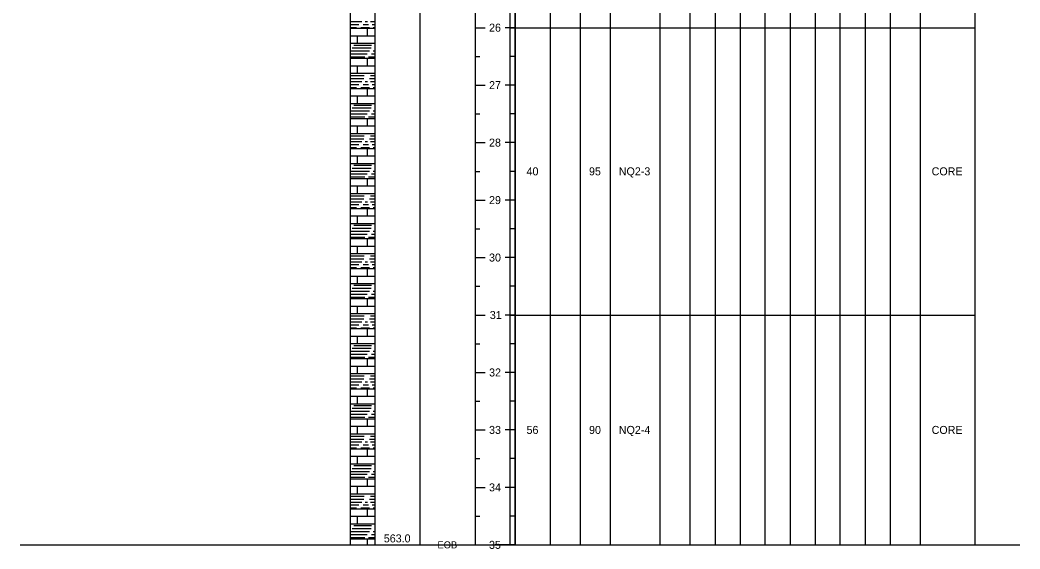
# Model space of a CAD drawing. Extents: x -0.01 to 0.83, y -0.48 to 1.27.
# Drawn here: x 0 to 0.833, y -0.482 to -0.041 of the extents above; entities that cross this region are included whole.
import ezdxf

# ---------------------------------------------------------------- set-up
doc = ezdxf.new("R2010")
doc.units = 0

msp = doc.modelspace()

# ---------------------------------------------------------------- linework, layer by layer
for points in [[(0.29583, 1.22083), (0.29583, -0.47833)], [(0.29583, 1.22083), (0.29583, -0.47833)], [(0.33333, 1.22083), (0.33333, -0.47833)], [(0.33333, 1.22083), (0.33333, -0.47833)], [(0.4125, 1.22083), (0.4125, -0.47833)], [(0.4125, 1.22083), (0.4125, -0.47833)], [(0.44167, 1.22083), (0.44167, -0.47833)], [(0.46667, 1.22083), (0.46667, -0.47833)], [(0.49167, 1.22083), (0.49167, -0.47833)], [(0.53333, 1.22083), (0.53333, -0.47833)], [(0.55833, 1.22083), (0.55833, -0.47833)], [(0.6625, 1.22083), (0.6625, -0.47833)], [(0.725, 1.22083), (0.725, -0.47833)], [(0.75, 1.22083), (0.75, -0.47833)], [(0.75, 1.22083), (0.75, -0.47833)], [(0.79583, 1.22083), (0.79583, -0.47833)], [(0.57917, 1.20833), (0.57917, -0.47833)], [(0.6, 1.20833), (0.6, -0.47833)], [(0.62083, 1.20833), (0.62083, -0.47833)], [(0.64167, 1.20833), (0.64167, -0.47833)], [(0.68333, 1.20833), (0.68333, -0.47833)], [(0.70417, 1.20833), (0.70417, -0.47833)], [(0.725, 1.20833), (0.725, -0.47833)], [(0.275, 1.19583), (0.275, -0.47833)], [(0.37917, 1.19583), (0.37917, -0.47833)], [(0.275, 0.23917), (0.275, -0.47833)], [(0.40833, 0.19133), (0.40833, -0.04783)], [(0.275, -0.04267), (0.28483, -0.04267)], [(0.275, -0.04508), (0.28233, -0.04508)], [(0.275, -0.04758), (0.28033, -0.04758)], [(0.275, -0.04833), (0.29583, -0.04833)], [(0.284, -0.04758), (0.29133, -0.04758)], [(0.286, -0.04508), (0.2905, -0.04508)], [(0.28767, -0.04267), (0.28967, -0.04267)], [(0.28958, -0.05458), (0.28958, -0.04833)], [(0.29217, -0.04267), (0.29583, -0.04267)], [(0.29342, -0.04508), (0.29583, -0.04508)], [(0.29417, -0.04758), (0.29583, -0.04758)], [(0.37917, -0.04783), (0.3875, -0.04783)], [(0.37917, -0.04783), (0.38333, -0.04783)], [(0.4125, -0.04783), (0.40417, -0.04783)], [(0.40833, -0.04783), (0.4125, -0.04783)], [(0.40833, -0.04783), (0.40833, -0.287)], [(0.40833, -0.04783), (0.4125, -0.04783)], [(0.4125, -0.04783), (0.40833, -0.04783)], [(0.4125, -0.04783), (0.44167, -0.04783)], [(0.44167, -0.04783), (0.46667, -0.04783)], [(0.46667, -0.04783), (0.49167, -0.04783)], [(0.49167, -0.04783), (0.53333, -0.04783)], [(0.53333, -0.04783), (0.55833, -0.04783)], [(0.55833, -0.04783), (0.57917, -0.04783)], [(0.57917, -0.04783), (0.6, -0.04783)], [(0.6, -0.04783), (0.62083, -0.04783)], [(0.62083, -0.04783), (0.64167, -0.04783)], [(0.64167, -0.04783), (0.6625, -0.04783)], [(0.6625, -0.04783), (0.68333, -0.04783)], [(0.68333, -0.04783), (0.70417, -0.04783)], [(0.70417, -0.04783), (0.725, -0.04783)], [(0.725, -0.04783), (0.75, -0.04783)], [(0.75, -0.04783), (0.79583, -0.04783)], [(0.275, -0.05458), (0.29583, -0.05458)], [(0.28125, -0.06083), (0.28125, -0.05458)], [(0.275, -0.06083), (0.29583, -0.06083)], [(0.27667, -0.06467), (0.29258, -0.06467)], [(0.27825, -0.06225), (0.293, -0.06225)], [(0.29542, -0.06225), (0.29583, -0.06225)], [(0.275, -0.06717), (0.29133, -0.06717)], [(0.275, -0.06958), (0.28933, -0.06958)], [(0.275, -0.07208), (0.28725, -0.07208)], [(0.275, -0.07333), (0.29583, -0.07333)], [(0.28958, -0.07958), (0.28958, -0.07333)], [(0.2905, -0.07208), (0.29583, -0.07208)], [(0.293, -0.06958), (0.29583, -0.06958)], [(0.29417, -0.06717), (0.29583, -0.06717)], [(0.37917, -0.07175), (0.38333, -0.07175)], [(0.4125, -0.07175), (0.40833, -0.07175)], [(0.275, -0.07958), (0.29583, -0.07958)], [(0.28125, -0.08583), (0.28125, -0.07958)], [(0.275, -0.08583), (0.29583, -0.08583)], [(0.275, -0.08775), (0.28683, -0.08775)], [(0.275, -0.09025), (0.28642, -0.09025)], [(0.29133, -0.09025), (0.29583, -0.09025)], [(0.29217, -0.08775), (0.29583, -0.08775)], [(0.275, -0.09267), (0.28483, -0.09267)], [(0.275, -0.09508), (0.28233, -0.09508)], [(0.275, -0.09758), (0.28033, -0.09758)], [(0.275, -0.09833), (0.29583, -0.09833)], [(0.284, -0.09758), (0.29133, -0.09758)], [(0.286, -0.09508), (0.2905, -0.09508)], [(0.28767, -0.09267), (0.28967, -0.09267)], [(0.28958, -0.10458), (0.28958, -0.09833)], [(0.29217, -0.09267), (0.29583, -0.09267)], [(0.29342, -0.09508), (0.29583, -0.09508)], [(0.29417, -0.09758), (0.29583, -0.09758)], [(0.37917, -0.09567), (0.3875, -0.09567)], [(0.37917, -0.09567), (0.38333, -0.09567)], [(0.4125, -0.09567), (0.40417, -0.09567)], [(0.4125, -0.09567), (0.40833, -0.09567)], [(0.275, -0.10458), (0.29583, -0.10458)], [(0.28125, -0.11083), (0.28125, -0.10458)], [(0.275, -0.11083), (0.29583, -0.11083)], [(0.27667, -0.11467), (0.29258, -0.11467)], [(0.27825, -0.11225), (0.293, -0.11225)], [(0.29542, -0.11225), (0.29583, -0.11225)], [(0.275, -0.11717), (0.29133, -0.11717)], [(0.275, -0.11958), (0.28933, -0.11958)], [(0.275, -0.12208), (0.28725, -0.12208)], [(0.275, -0.12333), (0.29583, -0.12333)], [(0.28958, -0.12958), (0.28958, -0.12333)], [(0.2905, -0.12208), (0.29583, -0.12208)], [(0.293, -0.11958), (0.29583, -0.11958)], [(0.29417, -0.11717), (0.29583, -0.11717)], [(0.37917, -0.11958), (0.38333, -0.11958)], [(0.4125, -0.11958), (0.40833, -0.11958)], [(0.275, -0.12958), (0.29583, -0.12958)], [(0.28125, -0.13583), (0.28125, -0.12958)], [(0.275, -0.13583), (0.29583, -0.13583)], [(0.275, -0.13775), (0.28683, -0.13775)], [(0.275, -0.14025), (0.28642, -0.14025)], [(0.29133, -0.14025), (0.29583, -0.14025)], [(0.29217, -0.13775), (0.29583, -0.13775)], [(0.275, -0.14267), (0.28483, -0.14267)], [(0.275, -0.14508), (0.28233, -0.14508)], [(0.275, -0.14758), (0.28033, -0.14758)], [(0.275, -0.14833), (0.29583, -0.14833)], [(0.284, -0.14758), (0.29133, -0.14758)], [(0.286, -0.14508), (0.2905, -0.14508)], [(0.28767, -0.14267), (0.28967, -0.14267)], [(0.28958, -0.15458), (0.28958, -0.14833)], [(0.29217, -0.14267), (0.29583, -0.14267)], [(0.29342, -0.14508), (0.29583, -0.14508)], [(0.29417, -0.14758), (0.29583, -0.14758)], [(0.37917, -0.1435), (0.3875, -0.1435)], [(0.37917, -0.1435), (0.38333, -0.1435)], [(0.4125, -0.1435), (0.40417, -0.1435)], [(0.4125, -0.1435), (0.40833, -0.1435)], [(0.275, -0.15458), (0.29583, -0.15458)], [(0.28125, -0.16083), (0.28125, -0.15458)], [(0.275, -0.16083), (0.29583, -0.16083)], [(0.27667, -0.16467), (0.29258, -0.16467)], [(0.27825, -0.16225), (0.293, -0.16225)], [(0.29542, -0.16225), (0.29583, -0.16225)], [(0.275, -0.16717), (0.29133, -0.16717)], [(0.275, -0.16958), (0.28933, -0.16958)], [(0.275, -0.17208), (0.28725, -0.17208)], [(0.275, -0.17333), (0.29583, -0.17333)], [(0.28958, -0.17958), (0.28958, -0.17333)], [(0.2905, -0.17208), (0.29583, -0.17208)], [(0.293, -0.16958), (0.29583, -0.16958)], [(0.29417, -0.16717), (0.29583, -0.16717)], [(0.37917, -0.16742), (0.38333, -0.16742)], [(0.4125, -0.16742), (0.40833, -0.16742)], [(0.275, -0.17958), (0.29583, -0.17958)], [(0.28125, -0.18583), (0.28125, -0.17958)], [(0.275, -0.18583), (0.29583, -0.18583)], [(0.275, -0.18775), (0.28683, -0.18775)], [(0.275, -0.19025), (0.28642, -0.19025)], [(0.29133, -0.19025), (0.29583, -0.19025)], [(0.29217, -0.18775), (0.29583, -0.18775)], [(0.37917, -0.19133), (0.3875, -0.19133)], [(0.37917, -0.19133), (0.38333, -0.19133)], [(0.4125, -0.19133), (0.40417, -0.19133)], [(0.4125, -0.19133), (0.40833, -0.19133)], [(0.275, -0.19267), (0.28483, -0.19267)], [(0.275, -0.19508), (0.28233, -0.19508)], [(0.275, -0.19758), (0.28033, -0.19758)], [(0.275, -0.19833), (0.29583, -0.19833)], [(0.284, -0.19758), (0.29133, -0.19758)], [(0.286, -0.19508), (0.2905, -0.19508)], [(0.28767, -0.19267), (0.28967, -0.19267)], [(0.28958, -0.20458), (0.28958, -0.19833)], [(0.29217, -0.19267), (0.29583, -0.19267)], [(0.29342, -0.19508), (0.29583, -0.19508)], [(0.29417, -0.19758), (0.29583, -0.19758)], [(0.275, -0.20458), (0.29583, -0.20458)], [(0.28125, -0.21083), (0.28125, -0.20458)], [(0.275, -0.21083), (0.29583, -0.21083)], [(0.27667, -0.21467), (0.29258, -0.21467)], [(0.27825, -0.21225), (0.293, -0.21225)], [(0.29542, -0.21225), (0.29583, -0.21225)], [(0.37917, -0.21525), (0.38333, -0.21525)], [(0.4125, -0.21525), (0.40833, -0.21525)], [(0.275, -0.21717), (0.29133, -0.21717)], [(0.275, -0.21958), (0.28933, -0.21958)], [(0.275, -0.22208), (0.28725, -0.22208)], [(0.275, -0.22333), (0.29583, -0.22333)], [(0.28958, -0.22958), (0.28958, -0.22333)], [(0.2905, -0.22208), (0.29583, -0.22208)], [(0.293, -0.21958), (0.29583, -0.21958)], [(0.29417, -0.21717), (0.29583, -0.21717)], [(0.275, -0.22958), (0.29583, -0.22958)], [(0.28125, -0.23583), (0.28125, -0.22958)], [(0.275, -0.23583), (0.29583, -0.23583)], [(0.275, -0.23775), (0.28683, -0.23775)], [(0.275, -0.24025), (0.28642, -0.24025)], [(0.29133, -0.24025), (0.29583, -0.24025)], [(0.29217, -0.23775), (0.29583, -0.23775)], [(0.37917, -0.23917), (0.3875, -0.23917)], [(0.37917, -0.23917), (0.38333, -0.23917)], [(0.4125, -0.23917), (0.40417, -0.23917)], [(0.4125, -0.23917), (0.40833, -0.23917)], [(0.275, -0.24267), (0.28483, -0.24267)], [(0.275, -0.24508), (0.28233, -0.24508)], [(0.275, -0.24758), (0.28033, -0.24758)], [(0.275, -0.24833), (0.29583, -0.24833)], [(0.284, -0.24758), (0.29133, -0.24758)], [(0.286, -0.24508), (0.2905, -0.24508)], [(0.28767, -0.24267), (0.28967, -0.24267)], [(0.28958, -0.25458), (0.28958, -0.24833)], [(0.29217, -0.24267), (0.29583, -0.24267)], [(0.29342, -0.24508), (0.29583, -0.24508)], [(0.29417, -0.24758), (0.29583, -0.24758)], [(0.275, -0.25458), (0.29583, -0.25458)], [(0.28125, -0.26083), (0.28125, -0.25458)], [(0.275, -0.26083), (0.29583, -0.26083)], [(0.27667, -0.26467), (0.29258, -0.26467)], [(0.27825, -0.26225), (0.293, -0.26225)], [(0.29542, -0.26225), (0.29583, -0.26225)], [(0.37917, -0.26308), (0.38333, -0.26308)], [(0.4125, -0.26308), (0.40833, -0.26308)], [(0.275, -0.26717), (0.29133, -0.26717)], [(0.275, -0.26958), (0.28933, -0.26958)], [(0.275, -0.27208), (0.28725, -0.27208)], [(0.275, -0.27333), (0.29583, -0.27333)], [(0.28958, -0.27958), (0.28958, -0.27333)], [(0.2905, -0.27208), (0.29583, -0.27208)], [(0.293, -0.26958), (0.29583, -0.26958)], [(0.29417, -0.26717), (0.29583, -0.26717)], [(0.275, -0.27958), (0.29583, -0.27958)], [(0.28125, -0.28583), (0.28125, -0.27958)], [(0.275, -0.28583), (0.29583, -0.28583)], [(0.275, -0.28775), (0.28683, -0.28775)], [(0.275, -0.29025), (0.28642, -0.29025)], [(0.29133, -0.29025), (0.29583, -0.29025)], [(0.29217, -0.28775), (0.29583, -0.28775)], [(0.37917, -0.287), (0.3875, -0.287)], [(0.37917, -0.287), (0.38333, -0.287)], [(0.4125, -0.287), (0.40417, -0.287)], [(0.40833, -0.287), (0.4125, -0.287)], [(0.40833, -0.287), (0.40833, -0.47833)], [(0.40833, -0.287), (0.4125, -0.287)], [(0.4125, -0.287), (0.40833, -0.287)], [(0.4125, -0.287), (0.44167, -0.287)], [(0.44167, -0.287), (0.46667, -0.287)], [(0.46667, -0.287), (0.49167, -0.287)], [(0.49167, -0.287), (0.53333, -0.287)], [(0.53333, -0.287), (0.55833, -0.287)], [(0.55833, -0.287), (0.57917, -0.287)], [(0.57917, -0.287), (0.6, -0.287)], [(0.6, -0.287), (0.62083, -0.287)], [(0.62083, -0.287), (0.64167, -0.287)], [(0.64167, -0.287), (0.6625, -0.287)], [(0.6625, -0.287), (0.68333, -0.287)], [(0.68333, -0.287), (0.70417, -0.287)], [(0.70417, -0.287), (0.725, -0.287)], [(0.725, -0.287), (0.75, -0.287)], [(0.75, -0.287), (0.79583, -0.287)], [(0.275, -0.29267), (0.28483, -0.29267)], [(0.275, -0.29508), (0.28233, -0.29508)], [(0.275, -0.29758), (0.28033, -0.29758)], [(0.275, -0.29833), (0.29583, -0.29833)], [(0.284, -0.29758), (0.29133, -0.29758)], [(0.286, -0.29508), (0.2905, -0.29508)], [(0.28767, -0.29267), (0.28967, -0.29267)], [(0.28958, -0.30458), (0.28958, -0.29833)], [(0.29217, -0.29267), (0.29583, -0.29267)], [(0.29342, -0.29508), (0.29583, -0.29508)], [(0.29417, -0.29758), (0.29583, -0.29758)], [(0.275, -0.30458), (0.29583, -0.30458)], [(0.28125, -0.31083), (0.28125, -0.30458)], [(0.275, -0.31083), (0.29583, -0.31083)], [(0.27667, -0.31467), (0.29258, -0.31467)], [(0.27825, -0.31225), (0.293, -0.31225)], [(0.29542, -0.31225), (0.29583, -0.31225)], [(0.37917, -0.31092), (0.38333, -0.31092)], [(0.4125, -0.31092), (0.40833, -0.31092)], [(0.275, -0.31717), (0.29133, -0.31717)], [(0.275, -0.31958), (0.28933, -0.31958)], [(0.275, -0.32208), (0.28725, -0.32208)], [(0.275, -0.32333), (0.29583, -0.32333)], [(0.28958, -0.32958), (0.28958, -0.32333)], [(0.2905, -0.32208), (0.29583, -0.32208)], [(0.293, -0.31958), (0.29583, -0.31958)], [(0.29417, -0.31717), (0.29583, -0.31717)], [(0.275, -0.32958), (0.29583, -0.32958)], [(0.28125, -0.33583), (0.28125, -0.32958)], [(0.275, -0.33583), (0.29583, -0.33583)], [(0.275, -0.33775), (0.28683, -0.33775)], [(0.275, -0.34025), (0.28642, -0.34025)], [(0.29133, -0.34025), (0.29583, -0.34025)], [(0.29217, -0.33775), (0.29583, -0.33775)], [(0.37917, -0.33483), (0.3875, -0.33483)], [(0.37917, -0.33483), (0.38333, -0.33483)], [(0.4125, -0.33483), (0.40417, -0.33483)], [(0.4125, -0.33483), (0.40833, -0.33483)], [(0.275, -0.34267), (0.28483, -0.34267)], [(0.275, -0.34508), (0.28233, -0.34508)], [(0.275, -0.34758), (0.28033, -0.34758)], [(0.275, -0.34833), (0.29583, -0.34833)], [(0.284, -0.34758), (0.29133, -0.34758)], [(0.286, -0.34508), (0.2905, -0.34508)], [(0.28767, -0.34267), (0.28967, -0.34267)], [(0.28958, -0.35458), (0.28958, -0.34833)], [(0.29217, -0.34267), (0.29583, -0.34267)], [(0.29342, -0.34508), (0.29583, -0.34508)], [(0.29417, -0.34758), (0.29583, -0.34758)], [(0.275, -0.35458), (0.29583, -0.35458)], [(0.28125, -0.36083), (0.28125, -0.35458)], [(0.275, -0.36083), (0.29583, -0.36083)], [(0.27667, -0.36467), (0.29258, -0.36467)], [(0.27825, -0.36225), (0.293, -0.36225)], [(0.29542, -0.36225), (0.29583, -0.36225)], [(0.37917, -0.35875), (0.38333, -0.35875)], [(0.4125, -0.35875), (0.40833, -0.35875)], [(0.275, -0.36717), (0.29133, -0.36717)], [(0.275, -0.36958), (0.28933, -0.36958)], [(0.275, -0.37208), (0.28725, -0.37208)], [(0.275, -0.37333), (0.29583, -0.37333)], [(0.28958, -0.37958), (0.28958, -0.37333)], [(0.2905, -0.37208), (0.29583, -0.37208)], [(0.293, -0.36958), (0.29583, -0.36958)], [(0.29417, -0.36717), (0.29583, -0.36717)], [(0.275, -0.37958), (0.29583, -0.37958)], [(0.28125, -0.38583), (0.28125, -0.37958)], [(0.37917, -0.38267), (0.3875, -0.38267)], [(0.37917, -0.38267), (0.38333, -0.38267)], [(0.4125, -0.38267), (0.40417, -0.38267)], [(0.4125, -0.38267), (0.40833, -0.38267)], [(0.275, -0.38583), (0.29583, -0.38583)], [(0.275, -0.38775), (0.28683, -0.38775)], [(0.275, -0.39025), (0.28642, -0.39025)], [(0.29133, -0.39025), (0.29583, -0.39025)], [(0.29217, -0.38775), (0.29583, -0.38775)], [(0.275, -0.39267), (0.28483, -0.39267)], [(0.275, -0.39508), (0.28233, -0.39508)], [(0.275, -0.39758), (0.28033, -0.39758)], [(0.275, -0.39833), (0.29583, -0.39833)], [(0.284, -0.39758), (0.29133, -0.39758)], [(0.286, -0.39508), (0.2905, -0.39508)], [(0.28767, -0.39267), (0.28967, -0.39267)], [(0.28958, -0.40458), (0.28958, -0.39833)], [(0.29217, -0.39267), (0.29583, -0.39267)], [(0.29342, -0.39508), (0.29583, -0.39508)], [(0.29417, -0.39758), (0.29583, -0.39758)], [(0.275, -0.40458), (0.29583, -0.40458)], [(0.28125, -0.41083), (0.28125, -0.40458)], [(0.37917, -0.40658), (0.38333, -0.40658)], [(0.4125, -0.40658), (0.40833, -0.40658)], [(0.275, -0.41083), (0.29583, -0.41083)], [(0.27667, -0.41467), (0.29258, -0.41467)], [(0.27825, -0.41225), (0.293, -0.41225)], [(0.29542, -0.41225), (0.29583, -0.41225)], [(0.275, -0.41717), (0.29133, -0.41717)], [(0.275, -0.41958), (0.28933, -0.41958)], [(0.275, -0.42208), (0.28725, -0.42208)], [(0.275, -0.42333), (0.29583, -0.42333)], [(0.28958, -0.42958), (0.28958, -0.42333)], [(0.2905, -0.42208), (0.29583, -0.42208)], [(0.293, -0.41958), (0.29583, -0.41958)], [(0.29417, -0.41717), (0.29583, -0.41717)], [(0.275, -0.42958), (0.29583, -0.42958)], [(0.28125, -0.43583), (0.28125, -0.42958)], [(0.37917, -0.4305), (0.3875, -0.4305)], [(0.37917, -0.4305), (0.38333, -0.4305)], [(0.4125, -0.4305), (0.40417, -0.4305)], [(0.4125, -0.4305), (0.40833, -0.4305)], [(0.275, -0.43583), (0.29583, -0.43583)], [(0.275, -0.43775), (0.28683, -0.43775)], [(0.275, -0.44025), (0.28642, -0.44025)], [(0.29133, -0.44025), (0.29583, -0.44025)], [(0.29217, -0.43775), (0.29583, -0.43775)], [(0.275, -0.44267), (0.28483, -0.44267)], [(0.275, -0.44508), (0.28233, -0.44508)], [(0.275, -0.44758), (0.28033, -0.44758)], [(0.275, -0.44833), (0.29583, -0.44833)], [(0.284, -0.44758), (0.29133, -0.44758)], [(0.286, -0.44508), (0.2905, -0.44508)], [(0.28767, -0.44267), (0.28967, -0.44267)], [(0.28958, -0.45458), (0.28958, -0.44833)], [(0.29217, -0.44267), (0.29583, -0.44267)], [(0.29342, -0.44508), (0.29583, -0.44508)], [(0.29417, -0.44758), (0.29583, -0.44758)], [(0.275, -0.45458), (0.29583, -0.45458)], [(0.28125, -0.46083), (0.28125, -0.45458)], [(0.37917, -0.45442), (0.38333, -0.45442)], [(0.4125, -0.45442), (0.40833, -0.45442)], [(0.275, -0.46083), (0.29583, -0.46083)], [(0.27667, -0.46467), (0.29258, -0.46467)], [(0.27825, -0.46225), (0.293, -0.46225)], [(0.29542, -0.46225), (0.29583, -0.46225)], [(0.275, -0.46717), (0.29133, -0.46717)], [(0.275, -0.46958), (0.28933, -0.46958)], [(0.275, -0.47208), (0.28725, -0.47208)], [(0.275, -0.47333), (0.29583, -0.47333)], [(0.28958, -0.47833), (0.28958, -0.47333)], [(0.2905, -0.47208), (0.29583, -0.47208)], [(0.293, -0.46958), (0.29583, -0.46958)], [(0.29417, -0.46717), (0.29583, -0.46717)], [(0, -0.47833), (0.275, -0.47833)], [(0.275, -0.47833), (0.29583, -0.47833)], [(0.275, -0.47833), (0.29583, -0.47833)], [(0.29583, -0.47833), (0.33333, -0.47833)], [(0.33333, -0.47833), (0.37917, -0.47833)], [(0.37917, -0.47833), (0.4125, -0.47833)], [(0.37917, -0.47833), (0.3875, -0.47833)], [(0.37917, -0.47833), (0.38333, -0.47833)], [(0.37917, -0.47833), (0.39583, -0.47833)], [(0.4125, -0.47833), (0.39583, -0.47833)], [(0.4125, -0.47833), (0.40417, -0.47833)], [(0.40833, -0.47833), (0.4125, -0.47833)], [(0.40833, -0.47833), (0.4125, -0.47833)], [(0.4125, -0.47833), (0.40833, -0.47833)], [(0.4125, -0.47833), (0.44167, -0.47833)], [(0.44167, -0.47833), (0.46667, -0.47833)], [(0.46667, -0.47833), (0.49167, -0.47833)], [(0.49167, -0.47833), (0.53333, -0.47833)], [(0.53333, -0.47833), (0.55833, -0.47833)], [(0.55833, -0.47833), (0.57917, -0.47833)], [(0.57917, -0.47833), (0.6, -0.47833)], [(0.6, -0.47833), (0.62083, -0.47833)], [(0.62083, -0.47833), (0.64167, -0.47833)], [(0.64167, -0.47833), (0.6625, -0.47833)], [(0.6625, -0.47833), (0.68333, -0.47833)], [(0.68333, -0.47833), (0.70417, -0.47833)], [(0.70417, -0.47833), (0.725, -0.47833)], [(0.725, -0.47833), (0.75, -0.47833)], [(0.75, -0.47833), (0.79583, -0.47833)], [(0.79583, -0.47833), (0.83333, -0.47833)]]:
    msp.add_lwpolyline(points)
for points in [[(0.40833, -0.04783), (0.4125, -0.04783), (0.4125, 0.19133), (0.40833, 0.19133)], [(0.40833, -0.287), (0.4125, -0.287), (0.4125, -0.04783), (0.40833, -0.04783)], [(0.40833, -0.47833), (0.4125, -0.47833), (0.4125, -0.287), (0.40833, -0.287)]]:
    msp.add_lwpolyline(points, close=True)

# ---------------------------------------------------------------- texts
for s, height, p in [('26', 0.006667, (0.39087, -0.05117)), ('27', 0.006667, (0.39087, -0.099)), ('28', 0.006667, (0.39086, -0.14683)), ('40', 0.006667, (0.42213, -0.17075)), ('95', 0.006667, (0.47417, -0.17075)), ('NQ2-3', 0.006667, (0.499, -0.17075)), ('CORE', 0.006667, (0.75971, -0.17075)), ('29', 0.006667, (0.39086, -0.19467)), ('30', 0.006667, (0.39088, -0.2425)), ('31', 0.006667, (0.39151, -0.29033)), ('32', 0.006667, (0.3909, -0.33817)), ('33', 0.006667, (0.39087, -0.386)), ('56', 0.006667, (0.42212, -0.386)), ('90', 0.006667, (0.47421, -0.386)), ('NQ2-4', 0.006667, (0.49901, -0.386)), ('CORE', 0.006667, (0.75971, -0.386)), ('34', 0.006667, (0.39088, -0.43383)), ('563.0', 0.006667, (0.30316, -0.47629)), ('35', 0.006667, (0.39084, -0.48167)), ('EOB', 0.005833, (0.34786, -0.48125))]:
    msp.add_text(s, height=height).set_placement(p)

doc.saveas('drawing.dxf')
